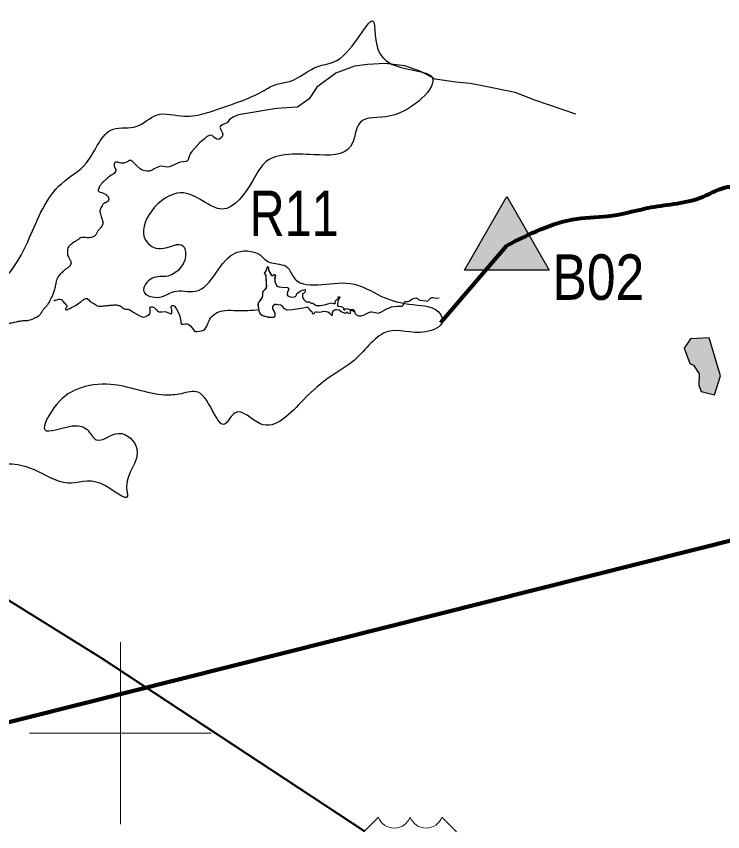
# Model space of a CAD drawing. Extents: x 553962 to 842807, y 8883888 to 9032388.
# Drawn here: x 673855 to 681625, y 8973918 to 8982880 of the extents above; entities that cross this region are included whole.
import ezdxf
from ezdxf.enums import TextEntityAlignment as Align

# ---------------------------------------------------------------- set-up
doc = ezdxf.new("R2010")
doc.units = 0
doc.header["$LTSCALE"] = 200
for name, color, linetype, lineweight in [('12', 7, 'Continuous', 25), ('2', 7, 'Continuous', 13), ('21', 7, 'Continuous', 25), ('24', 7, 'Continuous', 25), ('48', 7, 'Continuous', 25), ('50', 7, 'Continuous', 80), ('51', 7, 'Continuous', 25), ('52', 7, 'Continuous', 25), ('9', 7, 'Continuous', 90)]:
    doc.layers.add(name, color=color, linetype=linetype, lineweight=lineweight)
doc.layers.add('53', color=7, linetype='Continuous')

msp = doc.modelspace()

# ---------------------------------------------------------------- hatches: boundary and pattern name
at = {"layer": '21'}
msp.add_hatch(color=256, dxfattribs=at).paths.add_polyline_path([(681533.6, 8978720.1), (681601.7, 8978928.6), (681474.4, 8979344.4), (681268.6, 8979336), (681201.4, 8979231.2), (681264.6, 8979064.1), (681303.5, 8979046.7), (681367.3, 8978951), (681362.8, 8978827), (681387.7, 8978755.4)])
at = {"layer": '52'}
msp.add_hatch(color=256, dxfattribs=at).paths.add_polyline_path([(679249.2, 8980898), (679715.4, 8980090.7), (678783.1, 8980090.7)])

# ---------------------------------------------------------------- linework, layer by layer
at = {"layer": '12', "lineweight": 40}
msp.add_lwpolyline([(664631.3, 8982143.9), (674788, 8975827.4), (677683.8, 8973924.7)], dxfattribs=at)
at = {"layer": '2'}
for p, q in [((675000, 8974000), (675000, 8976000)), ((674000, 8975000), (676000, 8975000))]:
    msp.add_line(p, q, dxfattribs=at)
at = {"layer": '21'}
msp.add_lwpolyline([(681533.6, 8978720.1), (681601.7, 8978928.6), (681474.4, 8979344.4), (681268.6, 8979336), (681201.4, 8979231.2), (681264.6, 8979064.1), (681303.5, 8979046.7), (681367.3, 8978951), (681362.8, 8978827), (681387.7, 8978755.4)], close=True, dxfattribs=at)
at = {"layer": '24'}
for points in [[(680010.4, 8981805.1), (679556.9, 8981958.7), (679341.3, 8982043.7), (678998.1, 8982113.1), (678848.6, 8982142.2), (678687.8, 8982154.6), (678460.7, 8982189.8), (678306.2, 8982274.3), (678129.2, 8982336.8), (677913.1, 8982360.9), (677718.9, 8982351.5), (677574.5, 8982330.5), (677368.6, 8982254.7), (677162.1, 8982101.2), (677077.8, 8981974.5), (676949.4, 8981881.3), (676716.3, 8981866.7), (676299.8, 8981798.2), (676248, 8981776.3), (676201.9, 8981745.3), (676173.4, 8981709.8)], [(676173.4, 8981709.8), (676173, 8981709.2), (676157.8, 8981701.1), (676127.3, 8981691.6), (676101.8, 8981671.8), (676094.3, 8981657.4), (676100, 8981642), (676114.8, 8981613.2), (676125.1, 8981582.5), (676122.1, 8981566.5), (676114.4, 8981552.1), (676091.2, 8981529.2), (676075.5, 8981525.9), (676059.4, 8981529.4), (676032.2, 8981546.9), (676008.3, 8981568.8), (675992.5, 8981572.1), (675976.2, 8981569.3), (675946.6, 8981555.8), (675924.4, 8981532.2), (675899.5, 8981512.1), (675872.9, 8981493), (675787.7, 8981394.2), (675767.4, 8981368.2), (675755.3, 8981338.8), (675746.2, 8981307), (675737.7, 8981293.1), (675724.5, 8981284.2), (675659.3, 8981276.5), (675599.2, 8981251.5), (675539.1, 8981225.6), (675507.2, 8981222.6), (675475.2, 8981229.2)], [(675474, 8981229.5), (675446.5, 8981233.2), (675420.5, 8981226.1), (675370.6, 8981203.8), (675348.3, 8981188), (675322.3, 8981179), (675294.8, 8981178.1), (675267.7, 8981182.9), (675241.3, 8981190.6), (675217.6, 8981203.8), (675175.9, 8981239.8), (675137.9, 8981279), (675114.5, 8981294), (675101.3, 8981294.4), (675088.2, 8981289.5)], [(676735.1, 8979710.2), (676716.5, 8979713.3), (676699.8, 8979711.5), (676685.3, 8979701), (676673.4, 8979689.2), (676673.4, 8979670.8), (676681.3, 8979649.7), (676691.9, 8979635.3), (676697.1, 8979616.9), (676698.5, 8979598.5), (676695.8, 8979578.7), (676691.9, 8979570.9), (676670.8, 8979568.2), (676655, 8979568.2), (676631.3, 8979569.5), (676591.8, 8979578.7), (676557.6, 8979590.6), (676537.4, 8979611.3), (676526.2, 8979640.9), (676516.8, 8979711.5), (676518.1, 8979733.9), (676535.2, 8979749.7), (676548.4, 8979769.1), (676562.9, 8979792.8), (676566.8, 8979819.1), (676566.8, 8979833.5), (676568.2, 8979848), (676574.8, 8979859.8), (676593.2, 8979878.2), (676607.7, 8979899.2), (676607.7, 8979926.8), (676606.3, 8979975.5), (676605, 8980003.1), (676605, 8980020.2), (676598.4, 8980038.6), (676585.3, 8980057), (676599.8, 8980074.1), (676609, 8980103), (676616.9, 8980114.8), (676618.2, 8980128), (676626.1, 8980125.4), (676627.4, 8980108.3), (676629.1, 8980090.7), (676636.6, 8980075.4), (676656.4, 8980042.5), (676661.6, 8980030.7), (676673.5, 8980032), (676685.3, 8980039.9), (676695.9, 8980041.2), (676705.1, 8980028.1), (676697.2, 8980008.4), (676698.5, 8979987.3), (676698.5, 8979967.6), (676706.4, 8979943.9), (676716.9, 8979921.6), (676734, 8979909.8), (676749.8, 8979906.6)], [(677114.5, 8979604.9), (677115.1, 8979612.9), (677109.9, 8979626.4), (677088.3, 8979647.8), (677071.6, 8979672.7), (677058.5, 8979678.1), (677042.4, 8979678.5), (677011.8, 8979672.8), (676893.9, 8979653.4), (676833.5, 8979650.9), (676806.7, 8979663.1), (676786.2, 8979685), (676764.8, 8979705), (676734.4, 8979710.3), (676704, 8979712.9), (676679.2, 8979696.2), (676672.1, 8979684), (676673.9, 8979668.5), (676687.2, 8979642), (676697.5, 8979614.2), (676697.2, 8979584.4), (676691.5, 8979570.5), (676677.1, 8979567.8), (676646.6, 8979568.3), (676587.6, 8979579.8), (676559.2, 8979589.7), (676539.3, 8979608.2), (676527.7, 8979635), (676521.6, 8979666.9), (676517.9, 8979700.7), (676517.3, 8979732.2), (676538.4, 8979753.2), (676554.7, 8979778.5), (676566, 8979805.8), (676566.8, 8979835.9), (676569.1, 8979850.7), (676577.5, 8979863.1), (676599, 8979884.4), (676607, 8979897.2), (676609, 8979911.7), (676606.8, 8979942.2), (676605, 8980001.9), (676602.5, 8980031.5), (676585.3, 8980056.7), (676602.9, 8980080.8), (676605.9, 8980095.8), (676613.4, 8980108.1), (676616.7, 8980123.8), (676619.7, 8980128.2), (676626.8, 8980124.6), (676628.2, 8980093.8), (676656.8, 8980041), (676659.3, 8980033.3), (676664.7, 8980029.9), (676679.1, 8980035.7), (676692.6, 8980041.7), (676704.2, 8980032.5), (676701.9, 8980018), (676696.6, 8980004.1), (676698.3, 8979973.9), (676705.9, 8979945.2), (676719.6, 8979918.7), (676732.3, 8979910.4), (676746.8, 8979906.9), (676777, 8979904.4), (676836.4, 8979899), (676850.4, 8979891.1), (676851.1, 8979877.8), (676838.2, 8979849.8), (676834.1, 8979820.2), (676843.5, 8979808.4), (676856.4, 8979800.3), (676885, 8979792.4), (676915.7, 8979796.6), (676928.5, 8979805.1), (676935.4, 8979818.4), (676939.9, 8979833), (676950.8, 8979842.2), (676975.9, 8979858.9), (677004.3, 8979868.5), (677017.3, 8979875.3), (677031.4, 8979875.7), (677031.6, 8979859.5), (677027.7, 8979845.7), (677003.2, 8979827.9), (677002, 8979798), (677015.4, 8979771.4), (677036.3, 8979750.6), (677048.8, 8979742.4), (677064.8, 8979742.1), (677080.2, 8979742.2), (677089.3, 8979731.5), (677101.6, 8979725.9), (677117.8, 8979725.7), (677142.9, 8979708.9), (677155.6, 8979701.6)], [(677155.6, 8979701.6), (677170.5, 8979699.7), (677200.8, 8979701.8), (677259.5, 8979713.3), (677316.6, 8979731.3), (677344.6, 8979722.9), (677361.8, 8979724.7), (677366.5, 8979727.8), (677363.7, 8979734.2), (677362.3, 8979749.5), (677372.1, 8979760.8), (677383.9, 8979769.2), (677397.3, 8979775.5), (677399.5, 8979782.8), (677396.3, 8979789.8), (677396.1, 8979795.5), (677404.7, 8979796.3), (677412.1, 8979791.8), (677413.3, 8979785.2), (677403.4, 8979772.9), (677389.9, 8979746.9), (677386.7, 8979716.6), (677386.8, 8979701.8), (677397.3, 8979692.6), (677427.6, 8979689.4), (677443, 8979683.4), (677453.8, 8979672.6), (677454.6, 8979657.8), (677461.1, 8979653.1), (677469.3, 8979653.2), (677476.8, 8979665.5), (677489, 8979668.4), (677523.5, 8979658.6), (677553.6, 8979659.1), (677567.5, 8979655.6), (677575.8, 8979641.4), (677575.5, 8979634.3), (677568.5, 8979633), (677556.3, 8979641.9), (677526.7, 8979644.7), (677525.7, 8979637.3), (677532.1, 8979633.1), (677533.9, 8979626.8), (677527.9, 8979622.2), (677518.5, 8979611.5), (677503.8, 8979615.5), (677494.3, 8979626.8), (677486.9, 8979625.8), (677482.3, 8979619.9), (677469.5, 8979612.2), (677457.2, 8979620), (677429.7, 8979631.4), (677407.4, 8979651.1), (677377.8, 8979653.9), (677362.2, 8979653.1), (677350.3, 8979644.9), (677337.8, 8979636.6), (677328.8, 8979624.6), (677327.9, 8979593.7), (677325.9, 8979591.1), (677321.2, 8979595.4), (677308.1, 8979611.2), (677282.1, 8979626.2), (677253.3, 8979633.9), (677223.3, 8979632.2), (677209.6, 8979626.2), (677194.8, 8979625.1), (677165.1, 8979628.9), (677150.2, 8979628.9), (677136.1, 8979624), (677129.1, 8979610.6), (677115.2, 8979605.2)], [(677574.7, 8979633.6), (677579.2, 8979618), (677589.5, 8979605.1), (677602, 8979594.2), (677617.3, 8979588.8), (677650, 8979586.2), (677679.8, 8979600), (677740, 8979626.6), (677754.9, 8979633.3), (677770.9, 8979630.5), (677803, 8979623.7), (677834.8, 8979618.1), (677866.2, 8979629.4), (677923.4, 8979661), (677983.4, 8979687.5), (678048.2, 8979693.8), (678080.8, 8979695), (678098.1, 8979695.7), (678110.9, 8979703.2), (678121.9, 8979734.2), (678131.9, 8979746.2), (678148.5, 8979745), (678164.7, 8979744.1), (678179, 8979752.6), (678205.7, 8979770.8), (678236.6, 8979781.6), (678253.3, 8979785.3), (678266.6, 8979777.3), (678279, 8979766.4), (678294.1, 8979760.1), (678326.5, 8979755.5), (678358.9, 8979753.7), (678375, 8979750.2), (678382.5, 8979752.8), (678387.1, 8979759.7), (678409.9, 8979782.6), (678425.2, 8979788.5), (678441.7, 8979789.2), (678473.9, 8979781.9), (678506.3, 8979785.6)], [(675087.2, 8979659.3), (675095, 8979655.6), (675114.1, 8979645.4), (675146.7, 8979624.2), (675208.2, 8979591.3), (675240.7, 8979575.2), (675257.5, 8979573.3), (675274.6, 8979579), (675305.8, 8979595.8), (675319.4, 8979607.2), (675327.3, 8979622.7), (675327.6, 8979658.2), (675323.6, 8979674.8), (675328.6, 8979681.6), (675337.3, 8979685.4), (675354.3, 8979685.1), (675371.1, 8979678.1), (675396.3, 8979653.2), (675408.5, 8979640.4), (675424, 8979631.9), (675459.2, 8979632.5), (675494.4, 8979633.6), (675528, 8979622.3), (675560.4, 8979608.1), (675566.2, 8979614.1), (675565.7, 8979622.9), (675567.7, 8979640.6), (675564.3, 8979657.6), (675557.1, 8979673.7), (675557, 8979691.4), (675570.5, 8979702.5), (675587.8, 8979702.3), (675600.7, 8979690.3), (675618.7, 8979659.8), (675651.8, 8979597.5), (675665.5, 8979528.3), (675666.5, 8979510.4), (675673.8, 8979496.2), (675691.8, 8979495.5), (675711.8, 8979499.3), (675729.3, 8979500.5), (675745.4, 8979495.8), (675773.5, 8979473.1), (675814.3, 8979417.8), (675820.2, 8979416.2)]]:
    msp.add_lwpolyline(points, dxfattribs=at)
for points in [[(675088.2, 8981289.5), (675084.6, 8981286.1), (675073.1, 8981281), (675059.7, 8981272.7), (675039.9, 8981265.7), (675019.6, 8981265.6), (674995.4, 8981268.7), (674982, 8981273.1), (674960.3, 8981278.1), (674940.6, 8981276.2), (674934.2, 8981266.7), (674930.4, 8981246.4), (674930.3, 8981233.3), (674939.2, 8981216.9), (674950, 8981194.1), (674950, 8981172.6), (674932.2, 8981151.7), (674910.5, 8981138.4), (674888.2, 8981126.9), (674870.8, 8981114.5), (674849.1, 8981094.2), (674823.7, 8981070.8), (674802, 8981051.2), (674784.8, 8981030.3), (674766.2, 8981002.1), (674758, 8980979.3), (674754.2, 8980961.6), (674762.4, 8980950.3), (674795.5, 8980943.4), (674824.7, 8980928.9), (674855.4, 8980911.6), (674866.2, 8980896.4), (674876.3, 8980876.2), (674874.2, 8980857.5), (674852.5, 8980838.7), (674834.8, 8980830.4), (674816.2, 8980826.5), (674798.8, 8980797.3), (674785.8, 8980771.4), (674778.7, 8980757.7), (674774.3, 8980746.3), (674774.3, 8980730.6), (674779.7, 8980710.9), (674789.6, 8980677.2), (674799.5, 8980647.8), (674809.4, 8980612.7), (674805.2, 8980583.2), (674774.2, 8980544.7), (674750.3, 8980520.8), (674739, 8980494.1), (674719.4, 8980460.5), (674681.4, 8980447.8), (674633.7, 8980443.5), (674600.1, 8980450.4), (674572.5, 8980450.3), (674553, 8980439), (674525.2, 8980417.8), (674494.6, 8980402.3), (674473.2, 8980385.5), (674449, 8980368.7), (674429.1, 8980349.2), (674417.7, 8980318.3), (674418.2, 8980300.5), (674418.2, 8980271.1), (674421.1, 8980248.6), (674435.4, 8980221.9), (674452.6, 8980193.8), (674461.2, 8980171.3), (674452.6, 8980146.1), (674437, 8980126.5), (674405.6, 8980106.4), (674374.2, 8980081.3), (674342.8, 8980050.5), (674311.5, 8980012.7), (674298.6, 8979983.2), (674290.1, 8979952.4), (674283, 8979903.3), (674270.2, 8979852.8), (674250.5, 8979810.5), (674243.8, 8979793.3), (674225.4, 8979755.1)], [(674225.4, 8979755.1), (674222.2, 8979749.1), (674211.1, 8979728.9), (674193.8, 8979701.7), (674168, 8979673.7), (674143.7, 8979647.1), (674129.5, 8979619.1), (674096.6, 8979574.2), (674050.8, 8979561.7), (674019.3, 8979542.1), (673990.7, 8979533.8), (673947.8, 8979533.8), (673904.9, 8979528.3), (673866.3, 8979522.8), (673814.8, 8979508.9), (673766.2, 8979501.9), (673727.5, 8979486.2), (673707.4, 8979468.8), (673695.9, 8979444.3), (673685.8, 8979419.8)], [(674269.9, 8979755.2), (674271, 8979755.6), (674281, 8979758.8), (674301.5, 8979764.1), (674322.1, 8979771.7), (674348.5, 8979771.6), (674363.3, 8979753.9), (674372.3, 8979741.2), (674378.3, 8979735)], [(674378.3, 8979735), (674384.3, 8979728.8), (674399.4, 8979716.5), (674413.6, 8979702), (674406.5, 8979679.2), (674395.3, 8979662.6), (674398.5, 8979650.6), (674415.9, 8979653.8), (674449.4, 8979671.4), (674501.4, 8979697.8), (674579.8, 8979752.3), (674601.8, 8979771.3), (674617.6, 8979782), (674634.1, 8979778.8), (674651.9, 8979763), (674669.8, 8979744), (674693.9, 8979732.5), (674719.3, 8979715.9), (674739.1, 8979699.9), (674757.5, 8979693.5), (674779.1, 8979691.4), (674805.7, 8979694.5), (674831.1, 8979699.4), (674872.3, 8979701.7), (674917.4, 8979707.8), (674962.5, 8979706.9), (674989.8, 8979703.6), (675008.2, 8979692.1), (675027.3, 8979672.9), (675045.8, 8979662.6), (675065.5, 8979660.6), (675080.1, 8979660.5), (675087.2, 8979659.3)]]:
    msp.add_open_spline(points, degree=3, dxfattribs=at)
msp.add_spline([(675820.2, 8979416.2), (675913.3, 8979430.9), (675996.6, 8979568.1), (676148.5, 8979646.5), (676280.7, 8979646.5), (676520.8, 8979656.2)], degree=3, dxfattribs=at)
at = {"layer": '48', "lineweight": 13}
for p, q in [((677677.4, 8973917.6), (677837.4, 8974077.5)), ((678536.7, 8974077.5), (678696.6, 8973917.6))]:
    msp.add_line(p, q, dxfattribs=at)
for centre in [(678012.2, 8974144.5), (678361.8, 8974144.5)]:
    msp.add_arc(centre, 187.2, 200.95927, 339.04073, dxfattribs=at)
at = {"layer": '50'}
msp.add_line((678523.9, 8979515.3), (679249.2, 8980359.8), dxfattribs=at)
msp.add_spline([(679249.2, 8980359.8), (680020.1, 8980653.9), (680410.9, 8980689.4), (680836.6, 8980780.7), (681407.5, 8980897.3), (681677.8, 8981003.8), (682241.4, 8980172), (682422.6, 8979867.7), (682703.8, 8979664.9), (683881.3, 8979700.3), (684673.2, 8979629.3), (685224.3, 8979680), (685679.8, 8979857.5), (685970, 8980019.7), (686380.6, 8980146.5), (686588.5, 8980155.5)], degree=3, dxfattribs=at)
at = {"layer": '51'}
msp.add_spline([(672995.5, 8978483.6), (672982.4, 8979532.4), (673551.5, 8979855.6), (673843.8, 8980147.9), (673997.6, 8980440.2), (674351.3, 8981040.3), (674628.2, 8981271.1), (674920.4, 8981640.4), (675181.9, 8981671.1), (675397.2, 8981794.2), (675706, 8981782), (675935.5, 8981814.8), (676104.8, 8981871.2), (676535.4, 8982040.4), (676720, 8982132.7), (676858.4, 8982163.5), (677181.4, 8982332.7), (677381.4, 8982394.3), (677781.3, 8982825.1), (677859.4, 8982460.1), (678427.8, 8982208.6), (677972.5, 8981785), (677637, 8981714), (677532.5, 8981450.2), (677126.8, 8981359), (676580.9, 8981262.6), (676456.1, 8981075), (676121.2, 8980760.6), (675662.3, 8980939.7), (675279.7, 8980414.7), (675443.7, 8980327.2), (675691.4, 8980354.9), (675716.6, 8980288.9), (675521.9, 8980025.2), (675345.3, 8979999), (675257.8, 8979856.8), (675431.3, 8979793), (675590.5, 8979854.9), (675823, 8979857.9), (676286, 8980286.5), (676567.9, 8980230.1), (676596.1, 8980201.9), (676746.4, 8980154.9), (676837.5, 8980120.4), (676900, 8980020.1), (677526.6, 8979944), (677872.7, 8979802), (678218.7, 8979710.7), (678519.7, 8979604.2), (678539.9, 8979533.2), (678354.9, 8979411.5), (677943.9, 8979416.6), (677574, 8979102.1), (677318.9, 8978924.6), (677013.9, 8978666), (676536.8, 8978402), (676263.5, 8978522.4), (676154.2, 8978402), (675856.2, 8978747.2), (675670.8, 8978732), (675485.4, 8978716.8), (674893.8, 8978833.5), (674528.1, 8978782.8), (674268.1, 8978574.8), (674168.5, 8978336.5), (674469.1, 8978377), (674629.6, 8978341.5), (674735.1, 8978224.9), (674980.5, 8978295.9), (675181.3, 8978128.5), (675067.3, 8977692.3), (675077.6, 8977606.1), (674786.5, 8977743.1), (674420.7, 8977748.2), (674054.5, 8977895.2), (673808.8, 8977956.1), (673588.3, 8977935.8), (673498.2, 8977905.4)], degree=3, dxfattribs=at)
at = {"layer": '52'}
msp.add_lwpolyline([(679249.2, 8980898), (679715.4, 8980090.7), (678783.1, 8980090.7)], close=True, dxfattribs=at)
at = {"layer": '9'}
msp.add_lwpolyline([(658746.8, 8975176), (664691.5, 8973777.5), (669474.2, 8974039.3), (694202.6, 8980257.8)], dxfattribs=at)

# ---------------------------------------------------------------- texts
at = {"layer": '53'}
for s, width, p in [('R11', 0.8, (676912, 8980463.8)), ('B02', 0.85, (680256.7, 8979763.4))]:
    msp.add_text(s, height=500, dxfattribs=dict(at, width=width)).set_placement(p, align=Align.CENTER)

doc.saveas('drawing.dxf')
